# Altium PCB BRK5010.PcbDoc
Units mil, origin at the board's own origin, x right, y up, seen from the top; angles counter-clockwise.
Board outline 5314.96 x 3937.01 mil, 2 copper layers (Top Layer, Bottom Layer), stack 64.8 mil thick; 23 components, 218 nets, 546 pads, 113 vias.
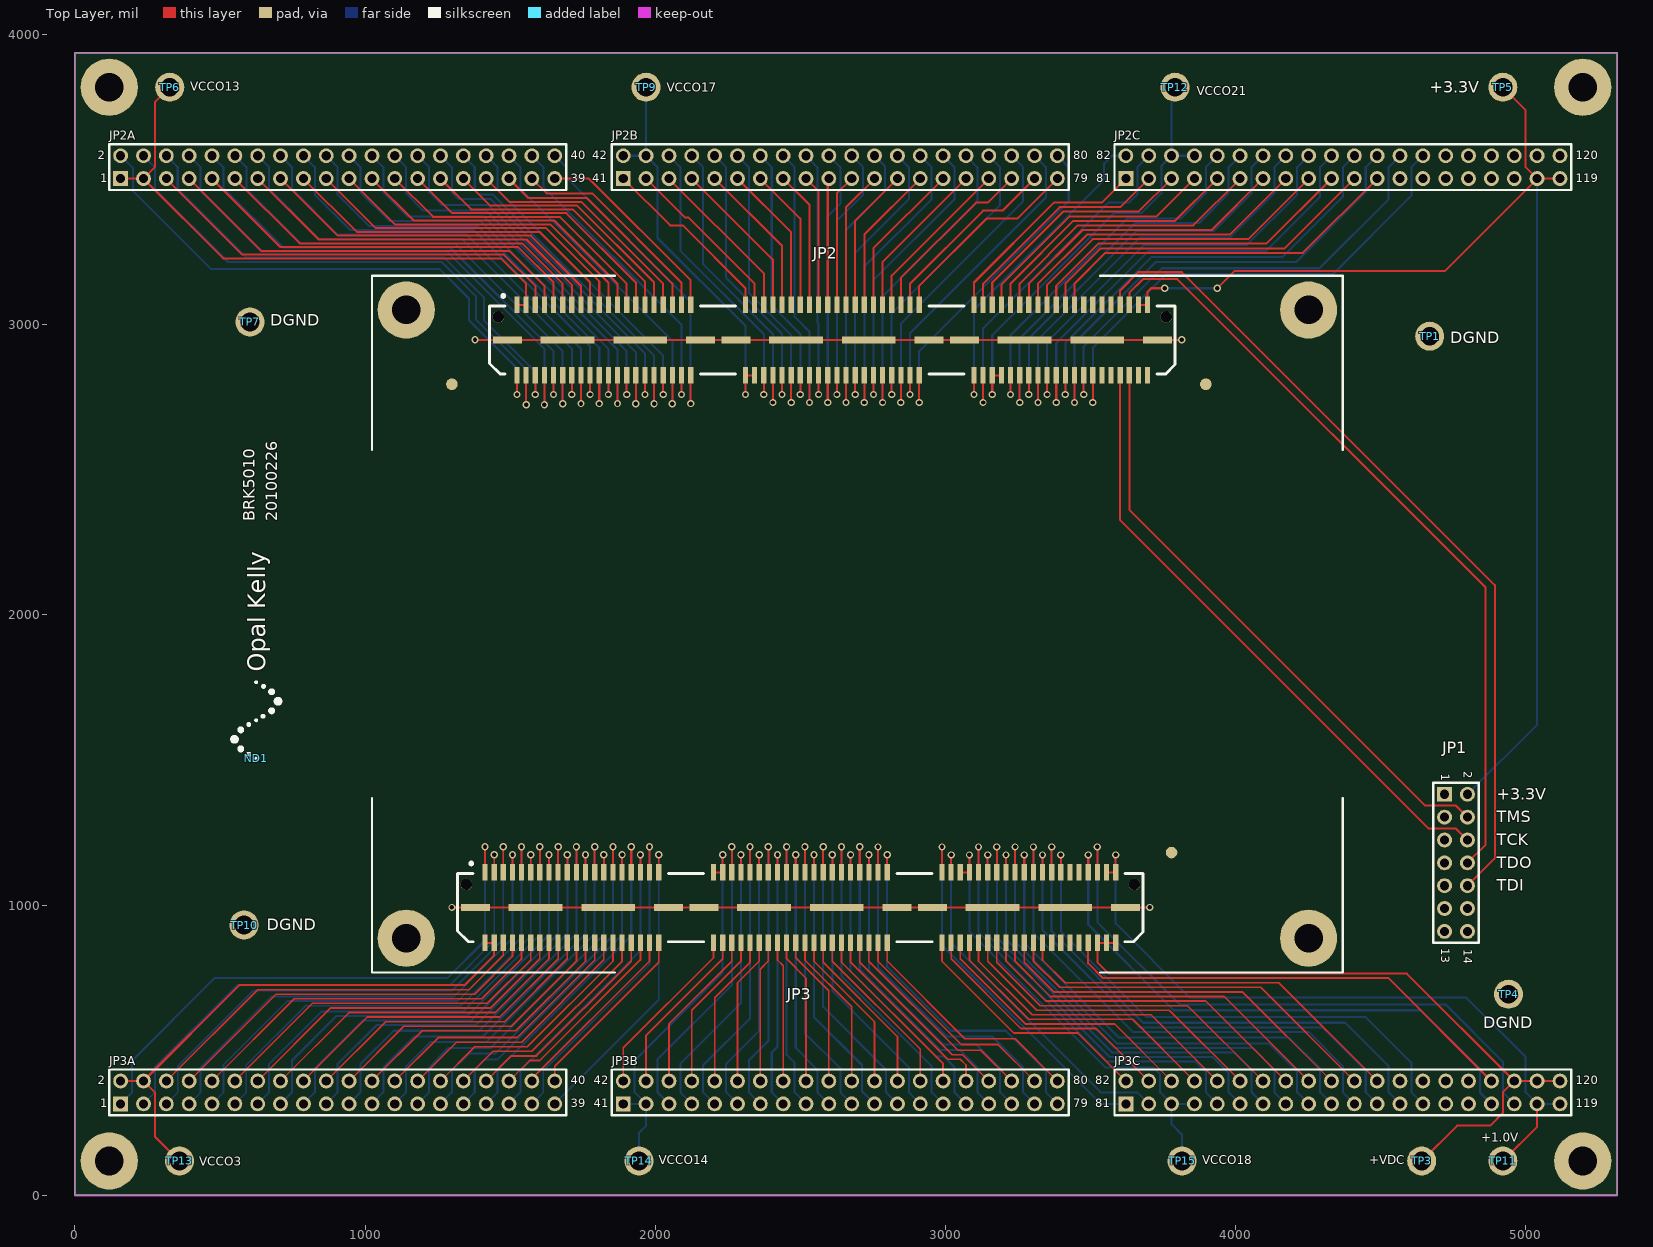
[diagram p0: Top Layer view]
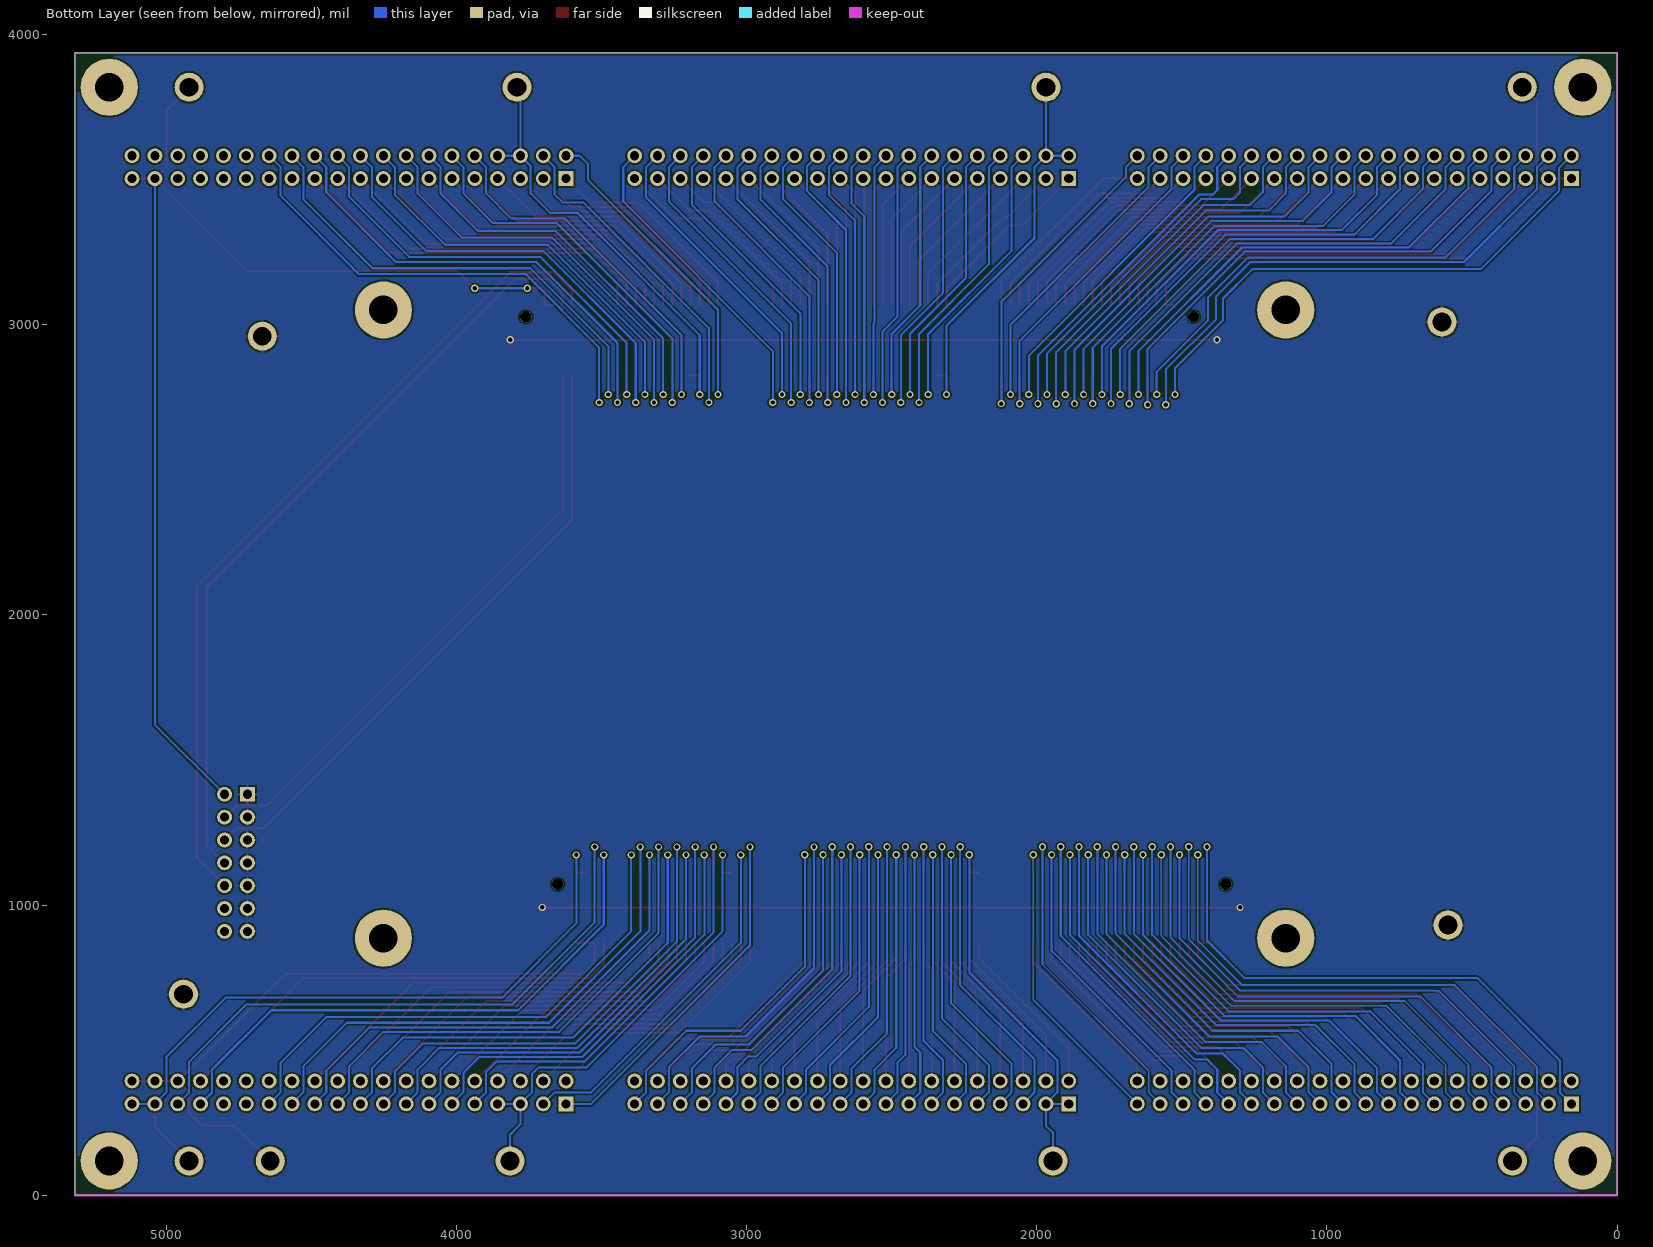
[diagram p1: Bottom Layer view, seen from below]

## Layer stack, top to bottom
Top Layer: signal copper 1.4
Dielectric: core 62, FR-4, Dk 4.8
Bottom Layer: signal copper 1.4

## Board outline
0,0 0,3937.01 5314.96,3937.01 5314.96,0

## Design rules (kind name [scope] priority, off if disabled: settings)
Clearance [All] p1: gap=6
FabricationTestPointUsage TestPointUsage [All] p1: valid=0 allowmultiple=FALSE
FabricationTestpoint Testpoint [All] p1: side=3 testpointundercomponent=TRUE minsize=40 maxsize=100 preferedsize=60 minholesize=0 maxholesize=40 preferedholesize=32 testpointgrid=1 allowsidetop=TRUE allowsidebottom=TRUE usegrid=TRUE gridtolerance=0.01
HoleSize [All] p1: absolutevalues=TRUE maxlimit=236.22 minlimit=15 maxpercent=80.000 minpercent=20.000
PolygonConnect "Via Connect" [IsVia] p1: connectstyle=Direct reliefconductorwidth=10 reliefentries=4 polygonreliefangle="90 Angle"
PolygonConnect [All] p2: connectstyle=Relief reliefconductorwidth=10 reliefentries=4 polygonreliefangle="90 Angle"
RoutingVias [All] p1: holewidth=15 width=25 viastyle="Through Hole" minholewidth=10 minwidth=20 maxholewidth=50 maxwidth=100
SilkscreenOverComponentPads [All] p1: minsilkscreentomaskgap=10
SolderMaskExpansion [All] p1: expansion=4
Width [All] p1: maxlimit=40 minlimit=6 preferedwidth=6 minimp=50.000000 maximp=50.000000 favimp=50.000000
24 further rules are at their usual default settings.

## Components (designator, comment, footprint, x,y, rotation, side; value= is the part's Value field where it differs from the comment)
JP1 "JTAGXLNX" HDR2X7-2MM 4759.84,1145.67 r270 top
JP2 "QSE/QTE-060" QTE-060-01-X-D 2216.61,2947.36 r0 top locked
JP2A "Header 20X2" HDR2X20-2MM 905.51,3543.31 r0 top
JP2B "Header 20X2" HDR2X20-2MM 2637.8,3543.31 r0 top
JP2C "Header 20X2" HDR2X20-2MM 4370.08,3543.31 r0 top
JP3 "QSE/QTE-060" QTE-060-01-X-D 2106.38,991.34 r0 top locked
JP3A "Header 20X2" HDR2X20-2MM 905.51,354.33 r0 top
JP3B "Header 20X2" HDR2X20-2MM 2637.8,354.33 r0 top
JP3C "Header 20X2" HDR2X20-2MM 4370.08,354.33 r0 top
ND1 "OKLOGO" oklogotiny 624.73,1505.69 r90 top
TP1 "TESTPOINT" TP_MED#1 4669.29,2960.63 r180 top
TP3 "TESTPOINT" TP_MED#1 4641.73,118.11 r180 top
TP4 "TESTPOINT" TP_MED#1 4940.94,692.91 r180 top
TP5 "TESTPOINT" TP_MED#1 4921.26,3818.9 r270 top
TP6 "TESTPOINT" TP_MED#1 326.77,3818.9 r180 top
TP7 "TESTPOINT" TP_MED#1 603.29,3009.77 r180 top
TP9 "TESTPOINT" TP_MED#1 1968.5,3818.9 r180 top
TP10 "TESTPOINT" TP_MED#1 582.88,931.15 r180 top
TP11 "TESTPOINT" TP_MED#2 5099.69,118.11 r180 top
TP12 "TESTPOINT" TP_MED#1 3791.34,3818.9 r180 top
TP13 "TESTPOINT" TP_MED#1 360,118.11 r180 top
TP14 "TESTPOINT" TP_MED#1 1943.92,118.11 r180 top
TP15 "TESTPOINT" TP_MED#1 3815.59,118.11 r180 top

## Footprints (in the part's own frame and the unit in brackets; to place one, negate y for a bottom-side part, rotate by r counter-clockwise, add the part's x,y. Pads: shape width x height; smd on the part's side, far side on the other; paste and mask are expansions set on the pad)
HDR2X7-2MM [mm] "2mm 2x7 header"
  rect 1.3x1.3 hole 0.8: 1(-6,-1)
  round 1.3 hole 0.8: 2(-6,1) 3(-4,-1) 4(-4,1) 5(-2,-1) 6(-2,1) 7(0,-1) 8(0,1) 9(2,-1) 10(2,1) 11(4,-1) 12(4,1) 13(6,-1) 14(6,1)
  silkscreen extent -7,-2 7,2
HDR2X20-2MM [mm] "2mm 2x20 header"
  rect 1.3x1.3 hole 0.8: 1(-19,-1)
  round 1.3 hole 0.8: 2(-19,1) 3(-17,-1) 4(-17,1) 5(-15,-1) 6(-15,1) 7(-13,-1) 8(-13,1) 9(-11,-1) 10(-11,1) 11(-9,-1) 12(-9,1) 13(-7,-1) 14(-7,1) 15(-5,-1) 16(-5,1) 17(-3,-1) 18(-3,1) 19(-1,-1) 20(-1,1) 21(1,-1) 22(1,1) 23(3,-1) 24(3,1) 25(5,-1) 26(5,1) 27(7,-1) 28(7,1) 29(9,-1) 30(9,1) 31(11,-1) 32(11,1) 33(13,-1) 34(13,1) 35(15,-1) 36(15,1) 37(17,-1) 38(17,1) 39(19,-1) 40(19,1)
  silkscreen extent -20,-2 20,2
oklogotiny [mil] "Opal Kelly silkscreen logo (50 mil)."
  silkscreen extent -3,-82 266,82
QTE-060-01-X-D [mil] "0.80mm, 120 pin Surface Mount connectors with Ground Strip"
  rect 100x25 smd paste+0: 0(-726.25,0) 0(-61.25,0) 0(61.25,0) 0(726.25,0) 0(848.75,0) 0(1513.75,0)
  rect 185x25 smd paste+0: 0(-518.75,0) 0(-268.75,0) 0(268.75,0) 0(518.75,0) 0(1056.25,0) 0(1306.25,0)
  rect 18x57 smd paste+0: 1(-693.05,121.5) 2(-693.05,-121.5) 3(-661.55,121.5) 4(-661.55,-121.5) 5(-630.05,121.5) 6(-630.05,-121.5) 7(-598.55,121.5) 8(-598.55,-121.5) 9(-567.05,121.5) 10(-567.05,-121.5) 11(-535.55,121.5) 12(-535.55,-121.5) 13(-504.05,121.5) 14(-504.05,-121.5) 15(-472.55,121.5) 16(-472.55,-121.5) 17(-441.05,121.5) 18(-441.05,-121.5) 19(-409.55,121.5) 20(-409.55,-121.5) 21(-378.05,121.5) 22(-378.05,-121.5) 23(-346.55,121.5) 24(-346.55,-121.5) 25(-315.05,121.5) 26(-315.05,-121.5) 27(-283.55,121.5) 28(-283.55,-121.5) 29(-252.05,121.5) 30(-252.05,-121.5) 31(-220.55,121.5) 32(-220.55,-121.5) 33(-189.05,121.5) 34(-189.05,-121.5) 35(-157.55,121.5) 36(-157.55,-121.5) 37(-126.05,121.5) 38(-126.05,-121.5) 39(-94.55,121.5) 40(-94.55,-121.5) 41(94.45,121.5) 42(94.45,-121.5) 43(125.95,121.5) 44(125.95,-121.5) 45(157.45,121.5) 46(157.45,-121.5) 47(188.95,121.5) 48(188.95,-121.5) 49(220.45,121.5) 50(220.45,-121.5) 51(251.95,121.5) 52(251.95,-121.5) 53(283.45,121.5) 54(283.45,-121.5) 55(314.95,121.5) 56(314.95,-121.5) 57(346.45,121.5) 58(346.45,-121.5) 59(377.95,121.5) 60(377.95,-121.5) 61(409.45,121.5) 62(409.45,-121.5) 63(440.95,121.5) 64(440.95,-121.5) 65(472.45,121.5) 66(472.45,-121.5) 67(503.95,121.5) 68(503.95,-121.5) 69(535.45,121.5) 70(535.45,-121.5) 71(566.95,121.5) 72(566.95,-121.5) 73(598.45,121.5) 74(598.45,-121.5) 75(629.95,121.5) 76(629.95,-121.5) 77(661.45,121.5) 78(661.45,-121.5) 79(692.95,121.5) 80(692.95,-121.5) 81(881.95,121.5) 82(881.95,-121.5) 83(913.45,121.5) 84(913.45,-121.5) 85(944.95,121.5) 86(944.95,-121.5) 87(976.45,121.5) 88(976.45,-121.5) 89(1007.95,121.5) 90(1007.95,-121.5) 91(1039.45,121.5) 92(1039.45,-121.5) 93(1070.95,121.5) 94(1070.95,-121.5) 95(1102.45,121.5) 96(1102.45,-121.5) 97(1133.95,121.5) 98(1133.95,-121.5) 99(1165.45,121.5) 100(1165.45,-121.5) 101(1196.95,121.5) 102(1196.95,-121.5) 103(1228.45,121.5) 104(1228.45,-121.5) 105(1259.95,121.5) 106(1259.95,-121.5) 107(1291.45,121.5) 108(1291.45,-121.5) 109(1322.95,121.5) 110(1322.95,-121.5) 111(1354.45,121.5) 112(1354.45,-121.5) 113(1385.95,121.5) 114(1385.95,-121.5) 115(1417.45,121.5) 116(1417.45,-121.5) 117(1448.95,121.5) 118(1448.95,-121.5) 119(1480.45,121.5) 120(1480.45,-121.5)
  round 40 hole 40 paste+0: N(-757.55,80) N(1544.95,80)
  silkscreen extent -788,-118 1575,157
TP_MED#1 [mil] "Testpoint - medium sized"
  round 100 hole 65: 1(0,0)
TP_MED#2 [mil] "Testpoint - medium sized"
  round 100 hole 65: 1(178.43,0)

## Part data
JP1: "Xilinx JTAG Header, 7-Pin, Dual row"
JP2 JP3: "Header/Socket - 120-pin - Edge mount, .80mm"
JP2A JP2B JP2C JP3A JP3B JP3C: "Header, 20-Pin, Dual row"
ND1: "Opal Kelly PCB Logo"
TP1 TP3 TP4 TP5 TP6 TP7 TP9 TP10 TP11 TP12 TP13 TP14 TP15: "Testpoint"

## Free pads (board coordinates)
  round 196.85 hole 98.43: 0(118.11,118.11) 0(118.11,3818.9) 0(1141.73,885.83) 0(1141.73,3051.18) 0(4251.97,885.83) 0(4251.97,3051.18) 0(5196.85,118.11) 0(5196.85,3818.9)
  round 40 smd mask+20: FD1(1299.21,2795.28) FD2(3897.64,2795.28) FD3(3779.53,1181.1)

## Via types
v1: diameter 25, hole 15, Top Layer to Bottom Layer, 113 vias

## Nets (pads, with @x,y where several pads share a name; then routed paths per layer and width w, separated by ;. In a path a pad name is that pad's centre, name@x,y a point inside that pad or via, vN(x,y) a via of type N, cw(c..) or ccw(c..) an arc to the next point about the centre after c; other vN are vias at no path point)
+1.0VDD: JP3.117 JP3.119 JP3C.37 JP3C.39 TP11.1 | length 2434
  Top Layer w7: JP3.117 JP3.119 v1(3586.83,1173.01) ; TP11.1 5039.37,236.22 JP3C.37
  Bottom Layer w7: v1(3586.83,1173.01) 3586.83,936.79 3842.52,681.1 4795.28,681.1 5000,476.38 5000,354.33 JP3C.37 JP3C.39
+3.3VDD: JP1.2 JP2.117 JP2.119 JP2C.37 JP2C.39 TP5.1 | length 4244.8
  Top Layer w7: JP2.117 JP2.119 3697.06,3114.39 3708.66,3125.98 v1(3755.91,3125.98) ; v1(3937.01,3125.98) 3996.06,3185.04 4720.47,3185.04 JP2C.37 ; TP5.1 5000,3740.16 5000,3543.31 JP2C.37 ; JP2C.39 JP2C.37
  Bottom Layer w7: v1(3755.91,3125.98) v1(3937.01,3125.98) ; JP1.2 5039.37,1622.05 JP2C.37
+VBATT: JP3.115 JP3C.35 | length 2105.9
  Top Layer w7: JP3.115 v1(3523.83,1200.58)
  Bottom Layer w7: v1(3523.83,1200.58) 3523.83,940.74 3807.09,657.48 4724.41,657.48 4921.26,460.63 4921.26,354.33 JP3C.35
+VCCO3: JP3.2 JP3.4 JP3A.2 JP3A.4 TP13.1 | length 1868.2
  Top Layer w7: JP3A.2 JP3A.4 ; TP13.1 275.59,202.52 275.59,354.33 JP3A.4 ; JP3.2 JP3.4 1444.83,826.72 1342.52,724.41 566.93,724.41 JP3A.4
+VCCO13: JP2.1 JP2.3 JP2A.1 JP2A.3 TP6.1 | length 2004.5
  Top Layer w7: JP2A.1 JP2A.3 ; TP6.1 275.59,3767.72 275.59,3543.31 JP2A.3 ; JP2.1 JP2.3 1555.06,3141.79 1467.84,3229.01 511.15,3229.01 JP2A.3
+VCCO14: JP3.41 JP3.43 JP3B.1 JP3B.3 TP14.1 | length 1377.7
  Top Layer w7: JP3.41 JP3.43 v1(2232.33,1173.18)
  Bottom Layer w7: JP3B.1 JP3B.3 ; TP14.1 1943.92,215.57 1968.5,240.16 JP3B.3 ; v1(2232.33,1173.18) 2232.33,767.76 1929.13,464.57 1929.13,354.33 JP3B.3
+VCCO17: JP2.42 JP2.44 JP2B.2 JP2B.4 TP9.1 | length 1377.2
  Top Layer w7: v1(2311.02,2759.84) v1(2311.02,2759.84) JP2.42 JP2.44
  Bottom Layer w7: JP2B.2 JP2B.4 ; TP9.1 JP2B.4 ; v1(2311.02,2759.84) 2311.02,2996.06 2007.87,3299.21 2007.87,3543.31 JP2B.4
+VCCO18: JP3.85 JP3.87 JP3C.5 JP3C.7 TP15.1 | length 1625.8
  Top Layer w7: JP3.85 JP3.87 v1(3082.83,1173.08)
  Bottom Layer w7: v1(3082.83,1173.08) 3082.83,909.3 3551.18,440.94 3716.54,440.94 3740.16,417.32 3740.16,354.33 JP3C.5 ; TP15.1 3815.59,208.03 3779.53,244.1 JP3C.5 ; JP3C.7 JP3C.5
+VCCO21: JP2.86 JP2.88 JP2C.6 JP2C.8 TP12.1 | length 1534.4
  Top Layer w7: v1(3161.56,2759.99) JP2.86 JP2.88
  Bottom Layer w7: v1(3161.56,2759.99) 3161.56,2964.55 3582.84,3385.83 3677.17,3385.83 3744.09,3452.76 3744.09,3547.24 JP2C.6 ; TP12.1@3779.53,3807.09 JP2C.6 ; JP2C.8 JP2C.6
+VDC: JP3.116 JP3.118 JP3.120 JP3C.36 JP3C.38 JP3C.40 TP3.1 | length 2368.3
  Top Layer w7: JP3.120 JP3.118 JP3.116 3523.83,802.94 3562.99,763.78 4590.55,763.78 JP3C.36 ; TP3.1 4763.78,240.16 4877.95,240.16 4921.26,283.46 4921.26,354.33 JP3C.36 ; JP3C.40 JP3C.38 JP3C.36
DGND: JP1.1 JP1.3 JP1.5 JP1.7 JP1.9 JP1.11 JP1.13 JP2.0 JP3.0 TP1.1 TP4.1 TP7.1 TP10.1 | length 4843.4
  Top Layer w7: v1(1299.21,992.13) 1300,991.34 1380.13,991.34 1587.63,991.34 1837.63,991.34 2045.13,991.34 2167.63,991.34 2375.13,991.34 2625.13,991.34 2832.63,991.34 2955.13,991.34 3162.63,991.34 3412.63,991.34 3620.13,991.34 3703.94,991.34 v1(3704.72,992.13) ; v1(1378.98,2948.82) 1380.43,2947.36 1490.36,2947.36 1697.86,2947.36 1947.86,2947.36 2155.36,2947.36 2277.86,2947.36 2485.36,2947.36 2735.36,2947.36 2942.86,2947.36 3065.36,2947.36 3272.86,2947.36 3522.86,2947.36 3730.36,2947.36 3813.5,2947.36 v1(3814.96,2948.82)
JP2_2: JP2.2 JP2A.2 | length 1916.1
  Top Layer w7: v1(1523.56,2759.78) JP2.2
  Bottom Layer w7: JP2A.2 200.79,3539.37 200.79,3460.63 468.5,3192.91 1255.91,3192.91 1358.27,3090.55 1358.27,3015.75 1523.56,2850.45 v1(1523.56,2759.78)
JP2_4: JP2.4 JP2A.4 | length 1937.3
  Top Layer w7: JP2.4 1555.06,2724.46 v1(1555.12,2724.41)
  Bottom Layer w7: JP2A.4 275.59,3543.31 275.59,3468.5 527.56,3216.54 1263.78,3216.54 1381.89,3098.43 1381.89,3019.68 1555.12,2846.46 v1(1555.12,2724.41)
JP2_5: JP2.5 JP2A.5 | length 1489.9
  Top Layer w7: JP2A.5 576.89,3242.01 1478.46,3242.01 1586.56,3133.91 JP2.5
JP2_6: JP2.6 JP2A.6 | length 1814.4
  Top Layer w7: v1(1586.56,2759.89) JP2.6
  Bottom Layer w7: JP2A.6 354.33,3543.31 354.33,3468.5 590.55,3232.28 1271.65,3232.28 1409.45,3094.49 1409.45,3015.75 1586.56,2838.63 v1(1586.56,2759.89)
JP2_7: JP2.7 JP2A.7 | length 1442.7
  Top Layer w7: JP2A.7 642.63,3255.01 1496.96,3255.01 1618.06,3133.9 JP2.7
JP2_8: JP2.8 JP2A.8 | length 1842.7
  Top Layer w7: v1(1618.06,2724.46) JP2.8
  Bottom Layer w7: JP2A.8 433.07,3543.31 433.07,3460.63 641.73,3251.97 1283.46,3251.97 1618.06,2917.37 v1(1618.06,2724.46)
JP2_9: JP2.9 JP2A.9 | length 1402.4
  Top Layer w7: JP2A.9 708.37,3268.01 1527.27,3268.01 1649.56,3145.71 JP2.9
JP2_10: JP2.10 JP2A.10 | length 1713.1
  Top Layer w7: v1(1649.56,2759.88) JP2.10
  Bottom Layer w7: JP2A.10 511.81,3543.31 511.81,3472.44 717.72,3266.53 1292.53,3266.53 1649.56,2909.49 v1(1649.56,2759.88)
JP2_11: JP2.11 JP2A.11 | length 1352.8
  Top Layer w7: JP2A.11 774.11,3281.01 1541.83,3281.01 1681.06,3141.77 JP2.11
JP2_12: JP2.12 JP2A.12 | length 1731.3
  Top Layer w7: v1(1681.06,2728.31) JP2.12
  Bottom Layer w7: JP2A.12 590.55,3543.31 590.55,3468.5 779.53,3279.53 1311.02,3279.53 1681.06,2909.49 v1(1681.06,2728.31)
JP2_13: JP2.13 JP2A.13 | length 1303.3
  Top Layer w7: JP2A.13 839.85,3294.01 1556.39,3294.01 1712.56,3137.83 JP2.13
JP2_14: JP2.14 JP2A.14 | length 1625.5
  Top Layer w7: v1(1712.56,2759.88) JP2.14
  Bottom Layer w7: JP2A.14 669.29,3543.31 669.29,3468.5 842.52,3295.28 1334.65,3295.28 1712.56,2917.36 v1(1712.56,2759.88)
JP2_15: JP2.15 JP2A.15 | length 1253.7
  Top Layer w7: JP2A.15 905.59,3307.01 1570.94,3307.01 1744.06,3133.89 JP2.15
JP2_16: JP2.16 JP2A.16 | length 1641.3
  Top Layer w7: v1(1744.06,2728.38) JP2.16
  Bottom Layer w7: JP2A.16 748.03,3543.31 748.03,3468.5 905.51,3311.02 1350.39,3311.02 1641.73,3019.68 1744.06,2917.35 v1(1744.06,2728.38)
JP2_17: JP2.17 JP2A.17 | length 1213.4
  Top Layer w7: JP2A.17 971.33,3320.01 1601.25,3320.01 1775.56,3145.7 JP2.17
JP2_18: JP2.18 JP2A.18 | length 1547.2
  Top Layer w7: v1(1775.56,2759.87) JP2.18
  Bottom Layer w7: JP2A.18 826.77,3543.31 826.77,3448.82 948.82,3326.77 1374.02,3326.77 1775.56,2925.22 v1(1775.56,2759.87)
JP2_19: JP2.19 JP2A.19 | length 1168.4
  Top Layer w7: JP2A.19 1037.07,3333.01 1623.68,3333.01 1807.06,3149.63 JP2.19
JP2_20: JP2.20 JP2A.20 | length 1560.6
  Top Layer w7: v1(1807.06,2728.37) JP2.20
  Bottom Layer w7: JP2A.20 905.51,3543.31 905.51,3448.82 1014.56,3339.77 1388.57,3339.77 1807.06,2921.28 v1(1807.06,2728.37)
JP2_21: JP2.21 JP2A.21 | length 1118.9
  Top Layer w7: JP2A.21 1102.81,3346.01 1638.24,3346.01 1838.56,3145.69 JP2.21
JP2_22: JP2.22 JP2A.22 | length 1443.5
  Top Layer w7: v1(1838.56,2759.86) JP2.22
  Bottom Layer w7: JP2A.22 984.25,3543.31 984.25,3456.69 1082.68,3358.27 1397.64,3358.27 1838.56,2917.34 v1(1838.56,2759.86)
JP2_23: JP2.23 JP2A.23 | length 1069.4
  Top Layer w7: JP2A.23 1168.55,3359.01 1652.8,3359.01 1870.06,3141.75 JP2.23
JP2_24: JP2.24 JP2A.24 | length 1456.9
  Top Layer w7: v1(1870.06,2728.36) JP2.24
  Bottom Layer w7: JP2A.24 1062.99,3543.31 1062.99,3456.69 1145.67,3374.02 1409.45,3374.02 1870.06,2913.4 v1(1870.06,2728.36)
JP2_25: JP2.25 JP2A.25 | length 1022.1
  Top Layer w7: JP2A.25 1234.29,3372.01 1671.3,3372.01 1901.56,3141.74 JP2.25
JP2_26: JP2.26 JP2A.26 | length 1346.7
  Top Layer w7: v1(1901.56,2759.85) JP2.26
  Bottom Layer w7: JP2A.26 1141.73,3543.31 1141.73,3452.76 1200.79,3393.7 1417.32,3393.7 1901.56,2909.46 v1(1901.56,2759.85)
JP2_27: JP2.27 JP2A.27 | length 977.2
  Top Layer w7: JP2A.27 1300.03,3385.01 1693.73,3385.01 1933.06,3145.68 JP2.27
JP2_28: JP2.28 JP2A.28 | length 1357.9
  Top Layer w7: v1(1933.06,2728.35) JP2.28
  Bottom Layer w7: JP2A.28 1220.47,3543.31 1220.47,3456.69 1263.78,3413.39 1425.2,3413.39 1933.06,2905.52 v1(1933.06,2728.35)
JP2_29: JP2.29 JP2A.29 | length 932.2
  Top Layer w7: JP2A.29 1365.77,3398.01 1716.17,3398.01 1964.56,3149.61 JP2.29
JP2_30: JP2.30 JP2A.30 | length 1245.3
  Top Layer w7: v1(1964.56,2759.85) JP2.30
  Bottom Layer w7: JP2A.30 1299.21,3543.31 1299.21,3456.69 1322.83,3433.07 1433.07,3433.07 1964.56,2901.58 v1(1964.56,2759.85)
JP2_31: JP2.31 JP2A.31 | length 882.7
  Top Layer w7: JP2A.31 1431.51,3411.01 1730.72,3411.01 1996.06,3145.67 JP2.31
JP2_32: JP2.32 JP2A.32 | length 1251.9
  Top Layer w7: v1(1996.06,2728.35) JP2.32
  Bottom Layer w7: JP2A.32 1377.95,3543.31 1377.95,3464.57 1393.7,3448.82 1440.94,3448.82 1996.06,2893.7 v1(1996.06,2728.35)
JP2_33: JP2.33 JP2A.33 | length 833.1
  Top Layer w7: JP2A.33 1497.25,3424.01 1745.28,3424.01 2027.56,3141.73 JP2.33
JP2_34: JP2.34 JP2A.34 | length 1141.6
  Top Layer w7: v1(2027.56,2759.85) JP2.34
  Bottom Layer w7: JP2A.34 1456.69,3543.31 1456.69,3464.57 2027.56,2893.7 v1(2027.56,2759.85)
JP2_35: JP2.35 JP2A.35 | length 785.9
  Top Layer w7: JP2A.35 1562.99,3437.01 1763.78,3437.01 2059.06,3141.72 JP2.35
JP2_36: JP2.36 JP2A.36 | length 1185
  Top Layer w7: v1(2059.06,2728.36) JP2.36
  Bottom Layer w7: JP2A.36 1535.43,3543.31 1535.43,3468.5 2059.06,2944.87 v1(2059.06,2728.36)
JP2_37: JP2.37 JP2A.37 | length 741
  Top Layer w7: JP2A.37 1625.98,3452.76 1783.46,3452.76 2090.56,3145.66 JP2.37
JP2_38: JP2.38 JP2A.38 | length 1102.5
  Top Layer w7: v1(2090.56,2759.86) JP2.38
  Bottom Layer w7: JP2A.38 1614.17,3543.31 1614.17,3476.38 2090.56,2999.99 v1(2090.56,2759.86)
JP2_39: JP2.39 JP2A.39 | length 698.3
  Top Layer w7: JP2A.39 1771.65,3503.94 2122.06,3153.53 JP2.39
JP2_40: JP2.40 JP2A.40 | length 1145.9
  Top Layer w7: v1(2122.06,2728.36) JP2.40
  Bottom Layer w7: JP2A.40 1692.91,3543.31 1692.91,3507.87 2122.06,3078.72 v1(2122.06,2728.36)
JP2_41: JP2.41 JP2B.1 | length 635
  Top Layer w7: JP2B.1 2051.18,3342.52 2094.49,3342.52 2311.06,3125.94 JP2.41
JP2_43: JP2.43 JP2B.3 | length 596.9
  Top Layer w7: JP2B.3 2102.36,3370.08 2114.17,3370.08 2342.56,3141.69 JP2.43
JP2_45: JP2.45 JP2B.5 | length 570.4
  Top Layer w7: JP2B.5 2374.06,3177.12 JP2.45
JP2_46: JP2.46 JP2B.6 | length 1024.1
  Top Layer w7: v1(2374.06,2759.89) JP2.46
  Bottom Layer w7: JP2B.6 2086.61,3543.31 2086.61,3255.91 2374.06,2968.46 v1(2374.06,2759.89)
JP2_47: JP2.47 JP2B.7 | length 550.9
  Top Layer w7: JP2B.7 2405.56,3224.36 JP2.47
JP2_48: JP2.48 JP2B.8 | length 1059.9
  Top Layer w7: v1(2405.56,2732.23) JP2.48
  Bottom Layer w7: JP2B.8 2165.35,3543.31 2165.35,3208.66 2405.56,2968.45 v1(2405.56,2732.23)
JP2_49: JP2.49 JP2B.9 | length 531.3
  Top Layer w7: JP2B.9 2437.06,3271.6 JP2.49
JP2_50: JP2.50 JP2B.10 | length 985
  Top Layer w7: v1(2437.06,2759.9) JP2.50
  Bottom Layer w7: JP2B.10 2244.09,3543.31 2244.09,3161.42 2437.06,2968.45 v1(2437.06,2759.9)
JP2_51: JP2.51 JP2B.11 | length 511.7
  Top Layer w7: JP2B.11 2468.56,3318.84 JP2.51
JP2_52: JP2.52 JP2B.12 | length 1020.5
  Top Layer w7: v1(2468.56,2732.34) JP2.52
  Bottom Layer w7: JP2B.12 2322.83,3543.31 2322.83,3110.24 2468.56,2964.51 v1(2468.56,2732.34)
JP2_53: JP2.53 JP2B.13 | length 492.2
  Top Layer w7: JP2B.13 2500.06,3366.08 JP2.53
JP2_54: JP2.54 JP2B.14 | length 945.8
  Top Layer w7: v1(2500.06,2759.91) JP2.54
  Bottom Layer w7: JP2B.14 2401.57,3543.31 2401.57,3066.93 2500.06,2968.44 v1(2500.06,2759.91)
JP2_55: JP2.55 JP2B.15 | length 472.6
  Top Layer w7: JP2B.15 2531.56,3413.32 JP2.55
JP2_56: JP2.56 JP2B.16 | length 981.4
  Top Layer w7: v1(2531.56,2732.35) JP2.56
  Bottom Layer w7: JP2B.16 2480.32,3543.31 2480.32,3027.56 2531.56,2976.31 v1(2531.56,2732.35)
JP2_57: JP2.57 JP2B.17 | length 453
  Top Layer w7: JP2B.17 2563.06,3460.56 JP2.57
JP2_58: JP2.58 JP2B.18 | length 906.7
  Top Layer w7: v1(2563.06,2759.91) JP2.58
  Bottom Layer w7: JP2B.18 2559.06,3543.31 2559.06,3007.87 2563.06,3003.87 v1(2563.06,2759.91)
JP2_59: JP2.59 JP2B.19 | length 436.7
  Top Layer w7: JP2.59 2594.56,3500.08 JP2B.19
JP2_60: JP2.60 JP2B.20 | length 978
  Top Layer w7: v1(2594.56,2732.36) JP2.60
  Bottom Layer w7: v1(2594.56,2732.36) 2594.56,3374.09 2637.8,3417.32 2637.8,3543.31 JP2B.20
JP2_61: JP2.61 JP2B.21 | length 456.2
  Top Layer w7: JP2.61 2626.06,3452.84 JP2B.21
JP2_62: JP2.62 JP2B.22 | length 942.5
  Top Layer w7: v1(2626.06,2759.92) JP2.62
  Bottom Layer w7: v1(2626.06,2759.92) 2626.06,3358.35 2716.54,3448.82 2716.54,3543.31 JP2B.22
JP2_63: JP2.63 JP2B.23 | length 475.8
  Top Layer w7: JP2.63 2657.56,3405.6 JP2B.23
JP2_64: JP2.64 JP2B.24 | length 1013.9
  Top Layer w7: v1(2657.56,2732.37) JP2.64
  Bottom Layer w7: v1(2657.56,2732.37) 2657.56,3326.86 2791.34,3460.63 2791.34,3547.24 JP2B.24
JP2_65: JP2.65 JP2B.25 | length 495.4
  Top Layer w7: JP2.65 2689.06,3358.36 JP2B.25
JP2_66: JP2.66 JP2B.26 | length 981.6
  Top Layer w7: v1(2689.06,2759.93) JP2.66
  Bottom Layer w7: v1(2689.06,2759.93) 2689.06,3248.12 2874.02,3433.07 2874.02,3543.31 JP2B.26
JP2_67: JP2.67 JP2B.27 | length 514.9
  Top Layer w7: JP2.67 2720.56,3311.12 JP2B.27
JP2_68: JP2.68 JP2B.28 | length 1056.3
  Top Layer w7: v1(2720.56,2732.38) JP2.68
  Bottom Layer w7: v1(2720.56,2732.38) 2720.56,3200.88 2952.76,3433.07 2952.76,3543.31 JP2B.28
JP2_69: JP2.69 JP2B.29 | length 534.5
  Top Layer w7: JP2.69 2752.06,3263.88 JP2B.29
JP2_70: JP2.70 JP2B.30 | length 1020.7
  Top Layer w7: v1(2752.06,2759.94) JP2.70
  Bottom Layer w7: v1(2752.06,2759.94) 2752.06,3153.64 3031.5,3433.07 3031.5,3543.31 JP2B.30
JP2_71: JP2.71 JP2B.31 | length 554.1
  Top Layer w7: JP2.71 2783.56,3216.64 JP2B.31
JP2_72: JP2.72 JP2B.32 | length 1095.4
  Top Layer w7: v1(2783.56,2732.38) JP2.72
  Bottom Layer w7: v1(2783.56,2732.38) 2783.56,3098.52 3110.24,3425.2 3110.24,3543.31 JP2B.32
JP2_73: JP2.73 JP2B.33 | length 573.6
  Top Layer w7: JP2.73 2815.06,3169.39 JP2B.33
JP2_74: JP2.74 JP2B.34 | length 1059.8
  Top Layer w7: v1(2815.06,2759.95) JP2.74
  Bottom Layer w7: v1(2815.06,2759.95) 2815.06,3039.47 3188.98,3413.39 3188.98,3543.31 JP2B.34
JP2_75: JP2.75 JP2B.35 | length 616.3
  Top Layer w7: JP2.75 2846.56,3161.52 3106.3,3421.26 3145.67,3421.26 JP2B.35
JP2_76: JP2.76 JP2B.36 | length 1134.5
  Top Layer w7: v1(2846.56,2732.39) JP2.76
  Bottom Layer w7: v1(2846.56,2732.39) 2846.56,3004.04 3267.72,3425.2 3267.72,3543.31 JP2B.36
JP2_77: JP2.77 JP2B.37 | length 652
  Top Layer w7: JP2.77 2878.06,3141.84 3129.92,3393.7 3196.85,3393.7 JP2B.37
JP2_78: JP2.78 JP2B.38 | length 1099
  Top Layer w7: v1(2878.06,2759.95) JP2.78
  Bottom Layer w7: v1(2878.06,2759.95) 2878.06,2970.49 3346.46,3438.88 3346.46,3543.31 JP2B.38
JP2_79: JP2.79 JP2B.39 | length 694.6
  Top Layer w7: JP2.79 2909.56,3133.97 3141.73,3366.14 3248.03,3366.14 JP2B.39
JP2_80: JP2.80 JP2B.40 | length 1173.6
  Top Layer w7: v1(2909.56,2732.4) JP2.80
  Bottom Layer w7: v1(2909.56,2732.4) 2909.56,2909.56 3425.2,3425.2 3425.2,3543.31 JP2B.40
JP2_81: JP2.81 JP2C.1 | length 748.8
  Top Layer w7: JP2.81 3098.56,3145.81 3374.02,3421.26 3539.37,3421.26 JP2C.1
JP2_82: JP2.82 JP2C.2 | length 1133.1
  Top Layer w7: v1(3098.56,2759.98) JP2.82
  Bottom Layer w7: v1(3098.56,2759.98) 3098.56,3051.32 3547.24,3500 3547.24,3555.12 3574.8,3582.68 JP2C.2
JP2_83: JP2.83 JP2C.3 | length 793.7
  Top Layer w7: JP2.83 3130.06,3141.88 3393.7,3405.51 3602.36,3405.51 JP2C.3
JP2_84: JP2.84 JP2C.4 | length 1221.6
  Top Layer w7: v1(3130.06,2732.43) JP2.84
  Bottom Layer w7: v1(3130.06,2732.43) 3130.06,2988.33 3563.53,3421.79 3634.39,3421.79 3661.42,3448.82 3661.42,3543.31 JP2C.4
JP2_85: JP2.85 JP2C.5 | length 843.3
  Top Layer w7: JP2.85 3161.56,3145.82 3405.51,3389.76 3665.35,3389.76 JP2C.5
JP2_86: JP2.90 JP2C.10 | length 1292.5
  Top Layer w7: v1(3224.41,2759.84) 3224.56,2760 JP2.90
  Bottom Layer w7: v1(3224.41,2759.84) 3224.41,2964.57 3625.98,3366.14 3811.02,3366.14 3897.64,3452.76 3897.64,3543.31 JP2C.10
JP2_87: JP2.87 JP2C.7 | length 885.9
  Top Layer w7: JP2.87 3193.06,3137.95 3429.13,3374.02 3728.35,3374.02 JP2C.7
JP2_88: JP2.92 JP2C.12 | length 1387.9
  Top Layer w7: v1(3255.91,2732.28) 3256.06,2732.44 JP2.92
  Bottom Layer w7: v1(3255.91,2732.28) 3255.91,2952.76 3653.54,3350.39 3874.02,3350.39 3976.38,3452.76 3976.38,3543.31 JP2C.12
JP2_89: JP2.89 JP2C.9 | length 935.4
  Top Layer w7: JP2.89 3224.56,3141.89 3440.94,3358.27 3791.34,3358.27 JP2C.9
JP2_90: JP2.94 JP2C.14 | length 1379.6
  Top Layer w7: v1(3287.56,2760) JP2.94
  Bottom Layer w7: v1(3287.56,2760) 3287.56,2952.92 3657.48,3322.83 3925.2,3322.83 4055.12,3452.76 4055.12,3543.31 JP2C.14
JP2_91: JP2.91 JP2C.11 | length 982.7
  Top Layer w7: JP2.91 3256.06,3141.89 3456.69,3342.52 3854.33,3342.52 JP2C.11
JP2_92: JP2.96 JP2C.16 | length 1479.6
  Top Layer w7: v1(3319.06,2732.45) JP2.96
  Bottom Layer w7: v1(3319.06,2732.45) 3319.06,2948.99 3671.26,3301.18 3982.28,3301.18 4133.86,3452.76 4133.86,3543.31 JP2C.16
JP2_93: JP2.93 JP2C.13 | length 1029.9
  Top Layer w7: JP2.93 3287.56,3141.89 3472.44,3326.77 3917.32,3326.77 JP2C.13
JP2_94: JP2.98 JP2C.18 | length 1469.4
  Top Layer w7: v1(3350.56,2760.01) JP2.98
  Bottom Layer w7: v1(3350.56,2760.01) 3350.56,2941.12 3685.04,3275.59 4039.37,3275.59 4212.6,3448.82 4212.6,3543.31 JP2C.18
JP2_95: JP2.95 JP2C.15 | length 1077.2
  Top Layer w7: JP2.95 3319.06,3141.9 3488.19,3311.02 3980.32,3311.02 JP2C.15
JP2_96: JP2.100 JP2C.20 | length 1574.1
  Top Layer w7: v1(3382.06,2732.46) JP2.100
  Bottom Layer w7: v1(3382.06,2732.46) 3382.06,2937.18 3698.82,3253.94 4104.33,3253.94 4291.34,3440.94 4291.34,3543.31 JP2C.20
JP2_97: JP2.97 JP2C.17 | length 1122.1
  Top Layer w7: JP2.97 3350.56,3137.97 3507.87,3295.28 4043.31,3295.28 JP2C.17
JP2_98: JP2.102 JP2C.22 | length 1566.2
  Top Layer w7: v1(3413.56,2760.02) JP2.102
  Bottom Layer w7: v1(3413.56,2760.02) 3413.56,2937.19 3710.63,3234.25 4163.39,3234.25 4370.08,3440.94 4370.08,3543.31 JP2C.22
JP2_99: JP2.99 JP2C.19 | length 1167
  Top Layer w7: JP2.99 3382.06,3134.03 3527.56,3279.53 4106.3,3279.53 JP2C.19
JP2_100: JP2.104 JP2C.24 | length 1659.4
  Top Layer w7: v1(3445.06,2732.47) JP2.104
  Bottom Layer w7: v1(3445.06,2732.47) 3445.06,2937.19 3724.41,3216.54 4208.66,3216.54 4448.82,3456.69 4448.82,3543.31 JP2C.24
JP2_101: JP2.101 JP2C.21 | length 1218.9
  Top Layer w7: JP2.101 3413.56,3141.91 3535.43,3263.78 4169.29,3263.78 JP2C.21
JP2_102: JP2.106 JP2C.26 | length 1658.4
  Top Layer w7: v1(3476.56,2760.03) JP2.106
  Bottom Layer w7: v1(3476.56,2760.03) 3476.56,2925.38 3746.06,3194.88 4289.37,3194.88 4527.56,3433.07 4527.56,3543.31 JP2C.26
JP2_103: JP2.103 JP2C.23 | length 1266.1
  Top Layer w7: JP2.103 3445.06,3141.91 3551.18,3248.03 4232.28,3248.03 JP2C.23
JP2_104: JP2.108 JP2C.28 | length 1751.5
  Top Layer w7: v1(3508.06,2732.47) JP2.108
  Bottom Layer w7: v1(3508.06,2732.47) 3508.06,2921.45 3761.81,3175.2 4336.61,3175.2 4606.3,3444.88 4606.3,3543.31 JP2C.28
JP3_1: JP3.1 JP3A.1 | length 1964.3
  Top Layer w7: JP3.1 v1(1413.33,1200.73)
  Bottom Layer w7: JP3A.1 196.85,354.33 196.85,464.57 480.31,748.03 1283.46,748.03 1413.33,877.89 v1(1413.33,1200.73)
JP3_3: JP3.3 JP3A.3 | length 1848.1
  Top Layer w6: JP3.3 v1(1444.83,1173.17)
  Bottom Layer w6: JP3A.3 275.59,354.33 275.59,440.94 559.06,724.41 1291.34,724.41 1444.83,877.9 v1(1444.83,1173.17)
JP3_5: JP3.5 JP3A.5 | length 1856
  Top Layer w6: JP3.5 v1(1476.33,1200.74)
  Bottom Layer w6: JP3A.5 354.33,354.33 354.33,444.88 614.17,704.72 1299.21,704.72 1476.33,881.84 v1(1476.33,1200.74)
JP3_6: JP3.6 JP3A.6 | length 1383.8
  Top Layer w6: JP3A.6 629.92,708.66 1358.27,708.66 1476.33,826.72 JP3.6
JP3_7: JP3.7 JP3A.7 | length 1749.1
  Top Layer w6: JP3.7 v1(1507.83,1173.18)
  Bottom Layer w6: JP3A.7 433.07,354.33 433.07,440.94 677.17,685.04 1307.09,685.04 1507.83,885.78 v1(1507.83,1173.18)
JP3_8: JP3.8 JP3A.8 | length 1338.9
  Top Layer w6: JP3A.8 692.91,692.91 1377.95,692.91 1507.83,822.79 JP3.8
JP3_9: JP3.9 JP3A.9 | length 1759.2
  Top Layer w6: JP3.9 v1(1539.33,1200.75)
  Bottom Layer w6: JP3A.9 511.81,354.33 511.81,448.82 732.28,669.29 1318.9,669.29 1539.33,889.72 v1(1539.33,1200.75)
JP3_10: JP3.10 JP3A.10 | length 1296.2
  Top Layer w6: JP3A.10 755.91,677.16 1401.49,677.16 1539.33,815 JP3.10
JP3_11: JP3.11 JP3A.11 | length 1654.6
  Top Layer w6: JP3.11 v1(1570.83,1173.19)
  Bottom Layer w6: JP3A.11 590.55,354.33 590.55,448.82 795.28,653.54 1330.71,653.54 1570.83,893.66 v1(1570.83,1173.19)
JP3_12: JP3.12 JP3A.12 | length 1251.3
  Top Layer w6: JP3A.12 818.9,661.42 1421.26,661.42 1570.83,810.99 JP3.12
JP3_13: JP3.13 JP3A.13 | length 1662.5
  Top Layer w7: JP3.13 v1(1602.33,1200.75)
  Bottom Layer w7: JP3A.13 669.29,354.33 669.29,452.76 850.39,633.86 1338.58,633.86 1602.33,897.6 v1(1602.33,1200.75)
JP3_14: JP3.14 JP3A.14 | length 1201.8
  Top Layer w6: JP3A.14 881.89,645.67 1433.07,645.67 1602.33,814.93 JP3.14
JP3_15: JP3.15 JP3A.15 | length 1567
  Top Layer w7: JP3.15 v1(1633.83,1173.2)
  Bottom Layer w7: JP3A.15 748.03,354.33 748.03,464.57 901.57,618.11 1354.33,618.11 1633.83,897.61 v1(1633.83,1173.2)
JP3_16: JP3.16 JP3A.16 | length 1154.6
  Top Layer w6: JP3A.16 944.88,629.92 1448.82,629.92 1633.83,814.93 JP3.16
JP3_17: JP3.17 JP3A.17 | length 1556.5
  Top Layer w7: JP3.17 v1(1665.33,1200.76)
  Bottom Layer w7: JP3A.17 826.77,354.33 826.77,437.01 992.13,602.36 1366.14,602.36 1665.33,901.55 v1(1665.33,1200.76)
JP3_18: JP3.18 JP3A.18 | length 1107.3
  Top Layer w6: JP3A.18 1007.87,614.17 1464.57,614.17 1665.33,814.93 JP3.18
JP3_19: JP3.19 JP3A.19 | length 1463.3
  Top Layer w7: JP3.19 v1(1696.83,1173.21)
  Bottom Layer w7: JP3A.19 905.51,354.33 905.51,452.76 1039.37,586.61 1381.89,586.61 1696.83,901.55 v1(1696.83,1173.21)
JP3_20: JP3.20 JP3A.20 | length 1060.1
  Top Layer w6: JP3A.20 1070.87,598.42 1480.31,598.42 1696.83,814.94 JP3.20
JP3_21: JP3.21 JP3A.21 | length 1471.2
  Top Layer w7: JP3.21 v1(1728.33,1200.77)
  Bottom Layer w7: JP3A.21 984.25,354.33 984.25,452.76 1098.43,566.93 1393.7,566.93 1728.33,901.56 v1(1728.33,1200.77)
JP3_22: JP3.22 JP3A.22 | length 1017.4
  Top Layer w6: JP3A.22 1133.86,582.68 1503.94,582.68 1728.33,807.07 JP3.22
JP3_23: JP3.23 JP3A.23 | length 1362
  Top Layer w7: JP3.23 v1(1759.83,1173.21)
  Bottom Layer w7: JP3A.23 1062.99,354.33 1062.99,440.94 1169.29,547.24 1405.51,547.24 1759.83,901.56 v1(1759.83,1173.21)
JP3_24: JP3.24 JP3A.24 | length 970.2
  Top Layer w6: JP3A.24 1196.85,566.93 1519.68,566.93 1759.83,807.07 JP3.24
JP3_25: JP3.25 JP3A.25 | length 1372.1
  Top Layer w7: JP3.25 v1(1791.33,1200.78)
  Bottom Layer w7: JP3A.25 1141.73,354.33 1141.73,444.88 1224.41,527.56 1417.32,527.56 1791.33,901.56 v1(1791.33,1200.78)
JP3_26: JP3.26 JP3A.26 | length 920.6
  Top Layer w6: JP3A.26 1251.97,543.31 1523.62,543.31 1791.33,811.01 JP3.26
JP3_27: JP3.27 JP3A.27 | length 1269.8
  Top Layer w7: JP3.27 v1(1822.83,1173.22)
  Bottom Layer w7: JP3A.27 1220.47,354.33 1220.47,440.94 1287.4,507.87 1433.07,507.87 1822.83,897.63 v1(1822.83,1173.22)
JP3_28: JP3.28 JP3A.28 | length 873.4
  Top Layer w6: JP3A.28 1314.96,527.56 1539.37,527.56 1822.83,811.02 JP3.28
JP3_29: JP3.29 JP3A.29 | length 1273.1
  Top Layer w7: JP3.29 v1(1854.33,1200.78)
  Bottom Layer w7: JP3A.29 1299.21,354.33 1299.21,429.13 1358.27,488.19 1448.82,488.19 1854.33,893.7 v1(1854.33,1200.78)
JP3_30: JP3.30 JP3A.30 | length 828.5
  Top Layer w6: JP3A.30 1377.95,511.81 1559.06,511.81 1854.33,807.08 JP3.30
JP3_31: JP3.31 JP3A.31 | length 1170.7
  Top Layer w7: JP3.31 v1(1885.83,1173.23)
  Bottom Layer w7: JP3A.31 1377.95,354.33 1377.95,433.07 1413.39,468.5 1456.69,468.5 1885.83,897.64 v1(1885.83,1173.23)
JP3_32: JP3.32 JP3A.32 | length 781.2
  Top Layer w6: JP3A.32 1440.94,496.06 1574.8,496.06 1885.83,807.09 JP3.32
JP3_33: JP3.33 JP3A.33 | length 1180.9
  Top Layer w7: JP3.33 v1(1917.33,1200.78)
  Bottom Layer w7: JP3A.33 1456.69,354.33 1456.69,433.07 1917.33,893.71 v1(1917.33,1200.78)
JP3_34: JP3.34 JP3A.34 | length 734
  Top Layer w6: JP3A.34 1503.94,480.31 1590.55,480.31 1917.33,807.09 JP3.34
JP3_35: JP3.35 JP3A.35 | length 1106.2
  Top Layer w7: JP3.35 v1(1948.83,1173.22)
  Bottom Layer w7: JP3A.35 1535.43,354.33 1535.43,429.13 1948.83,842.53 v1(1948.83,1173.22)
JP3_36: JP3.36 JP3A.36 | length 684.4
  Top Layer w6: JP3A.36 1566.93,464.57 1602.36,464.57 1948.83,811.03 JP3.36
JP3_37: JP3.37 JP3A.37 | length 1141.7
  Top Layer w6: JP3.37 v1(1980.33,1200.77)
  Bottom Layer w6: JP3A.37 1614.17,354.33 1614.17,429.13 1980.33,795.29 v1(1980.33,1200.77)
JP3_38: JP3.38 JP3A.38 | length 644.1
  Top Layer w6: JP3A.38 1574.8,401.58 1980.33,807.1 JP3.38
JP3_39: JP3.39 JP3A.39 | length 1067
  Top Layer w6: JP3.39 v1(2011.83,1173.21)
  Bottom Layer w6: JP3A.39 2011.83,673.24 v1(2011.83,1173.21)
JP3_40: JP3.40 JP3A.40 | length 624.5
  Top Layer w6: JP3A.40 1653.54,444.88 2011.83,803.17 JP3.40
JP3_42: JP3.42 JP3B.2 | length 605
  Top Layer w6: JP3B.2 1889.76,507.87 2200.83,818.94 JP3.42
JP3_44: JP3.44 JP3B.4 | length 585.4
  Top Layer w6: JP3B.4 1968.5,551.18 2232.33,815.01 JP3.44
JP3_45: JP3.45 JP3B.5 | length 1096
  Top Layer w7: JP3.45 v1(2263.83,1200.74)
  Bottom Layer w7: JP3B.5 2007.87,354.33 2007.87,468.5 2263.83,724.46 v1(2263.83,1200.74)
JP3_46: JP3.46 JP3B.6 | length 565.8
  Top Layer w6: JP3B.6 2047.24,590.55 2263.83,807.14 JP3.46
JP3_47: JP3.47 JP3B.7 | length 1021.3
  Top Layer w7: JP3.47 v1(2295.33,1173.18)
  Bottom Layer w7: JP3B.7 2086.61,354.33 2086.61,452.76 2295.33,661.47 v1(2295.33,1173.18)
JP3_48: JP3.48 JP3B.8 | length 546.3
  Top Layer w6: JP3B.8 2125.99,637.8 2295.33,807.14 JP3.48
JP3_49: JP3.49 JP3B.9 | length 1056.9
  Top Layer w7: JP3.49 v1(2326.83,1200.73)
  Bottom Layer w7: JP3B.9 2165.35,354.33 2165.35,448.82 2326.83,610.29 v1(2326.83,1200.73)
JP3_50: JP3.50 JP3B.10 | length 526.7
  Top Layer w6: JP3B.10 2204.73,681.1 2326.83,803.21 JP3.50
JP3_51: JP3.51 JP3B.11 | length 982.2
  Top Layer w7: JP3.51 v1(2358.33,1173.17)
  Bottom Layer w7: JP3B.11 2244.09,354.33 2244.09,452.76 2358.33,566.99 v1(2358.33,1173.17)
JP3_52: JP3.52 JP3B.12 | length 507.1
  Top Layer w6: JP3B.12 2283.47,732.28 2358.33,807.15 JP3.52
JP3_53: JP3.53 JP3B.13 | length 1017.7
  Top Layer w7: JP3.53 v1(2389.83,1200.72)
  Bottom Layer w7: JP3B.13 2322.83,354.33 2322.83,464.57 2389.83,531.56 v1(2389.83,1200.72)
JP3_54: JP3.54 JP3B.14 | length 487.6
  Top Layer w6: JP3B.14 2362.21,779.53 2389.83,807.15 JP3.54
JP3_55: JP3.55 JP3B.15 | length 943
  Top Layer w7: JP3.55 v1(2421.33,1173.16)
  Bottom Layer w7: v1(2421.33,1173.16) 2421.33,511.88 2401.57,492.13 2401.57,354.33 JP3B.15
JP3_56: JP3.56 JP3B.16 | length 484.3
  Top Layer w6: JP3.56 2421.33,810.96 2440.95,791.34 JP3B.16
JP3_57: JP3.57 JP3B.17 | length 1001.3
  Top Layer w7: JP3.57 v1(2452.83,1200.72)
  Bottom Layer w7: v1(2452.83,1200.72) 2452.83,484.18 2480.32,456.69 2480.32,354.33 JP3B.17
JP3_58: JP3.58 JP3B.18 | length 503.8
  Top Layer w6: JP3.58 2452.83,814.89 2519.69,748.03 JP3B.18
JP3_59: JP3.59 JP3B.19 | length 965.8
  Top Layer w7: JP3.59 v1(2484.33,1173.15)
  Bottom Layer w7: v1(2484.33,1173.15) 2484.33,507.8 2559.06,433.07 2559.06,354.33 JP3B.19
JP3_60: JP3.60 JP3B.20 | length 523.4
  Top Layer w6: JP3.60 2484.33,818.82 2598.43,704.72 JP3B.20
JP3_61: JP3.61 JP3B.21 | length 1040.4
  Top Layer w7: JP3.61 v1(2515.83,1200.71)
  Bottom Layer w7: v1(2515.83,1200.71) 2515.83,558.98 2637.8,437.01 2637.8,354.33 JP3B.21
JP3_62: JP3.62 JP3B.22 | length 543
  Top Layer w6: JP3.62 2515.83,810.94 2677.17,649.61 JP3B.22
JP3_63: JP3.63 JP3B.23 | length 1004.9
  Top Layer w7: JP3.63 v1(2547.33,1173.14)
  Bottom Layer w7: v1(2547.33,1173.14) 2547.33,614.09 2712.6,448.82 2712.6,358.27 JP3B.23
JP3_64: JP3.64 JP3B.24 | length 562.5
  Top Layer w6: JP3.64 2547.33,807 2755.91,598.43 JP3B.24
JP3_65: JP3.65 JP3B.25 | length 1079.6
  Top Layer w7: JP3.65 v1(2578.83,1200.7)
  Bottom Layer w7: v1(2578.83,1200.7) 2578.83,649.52 2795.28,433.07 2795.28,354.33 JP3B.25
JP3_66: JP3.66 JP3B.26 | length 582.1
  Top Layer w6: JP3.66 2578.83,803.06 2834.65,547.24 JP3B.26
JP3_67: JP3.67 JP3B.27 | length 1044
  Top Layer w7: JP3.67 v1(2610.33,1173.14)
  Bottom Layer w7: v1(2610.33,1173.14) 2610.33,704.63 2874.02,440.94 2874.02,354.33 JP3B.27
JP3_68: JP3.68 JP3B.28 | length 601.7
  Top Layer w6: JP3.68 2610.33,806.99 2913.39,503.94 JP3B.28
JP3_69: JP3.69 JP3B.29 | length 1118.7
  Top Layer w7: JP3.69 v1(2641.83,1200.69)
  Bottom Layer w7: v1(2641.83,1200.69) 2641.83,755.81 2952.76,444.88 2952.76,354.33 JP3B.29
JP3_70: JP3.70 JP3B.30 | length 621.2
  Top Layer w6: JP3.70 2641.83,803.25 2992.13,452.95 JP3B.30
JP3_71: JP3.71 JP3B.31 | length 1099.2
  Top Layer w7: JP3.71 v1(2673.33,1173.13)
  Bottom Layer w7: v1(2673.33,1173.13) 2673.33,771.75 2966.48,478.6 2993.85,478.6 3031.5,440.94 3031.5,354.33 JP3B.31
JP3_72: JP3.72 JP3B.32 | length 666.2
  Top Layer w6: JP3.72 2673.33,803.05 3007.87,468.5 3051.18,468.5 3070.87,448.82 JP3B.32
JP3_73: JP3.73 JP3B.33 | length 1197
  Top Layer w7: JP3.73 v1(2704.83,1200.68)
  Bottom Layer w7: v1(2704.83,1200.68) 2704.83,779.42 2984.25,500 3051.18,500 3110.24,440.94 3110.24,354.33 JP3B.33
JP3_74: JP3.74 JP3B.34 | length 681
  Top Layer w6: JP3.74 2704.83,803.25 3023.83,484.25 3059.06,484.25 JP3B.34
JP3_75: JP3.75 JP3B.35 | length 1189.1
  Top Layer w7: JP3.75 v1(2736.33,1173.12)
  Bottom Layer w7: v1(2736.33,1173.12) 2736.33,775.48 2992.13,519.68 3106.3,519.68 3188.98,437.01 3188.98,354.33 JP3B.35
JP3_76: JP3.76 JP3B.36 | length 726.1
  Top Layer w6: JP3.76 2736.33,806.98 3043.31,500 3122.05,500 JP3B.36
JP3_77: JP3.77 JP3B.37 | length 1289.2
  Top Layer w7: JP3.77 v1(2767.83,1200.68)
  Bottom Layer w7: v1(2767.83,1200.68) 2767.83,783.35 3003.94,547.24 3161.42,547.24 3267.72,440.94 3267.72,354.33 JP3B.37
JP3_78: JP3.78 JP3B.38 | length 773.3
  Top Layer w6: JP3.78 2767.83,806.98 3055.12,519.68 3181.1,519.68 JP3B.38
JP3_79: JP3.79 JP3B.39 | length 1272.1
  Top Layer w7: JP3.79 v1(2799.33,1173.11)
  Bottom Layer w7: v1(2799.33,1173.11) 2799.33,787.29 3019.69,566.93 3208.66,566.93 3346.46,429.13 3346.46,354.33 JP3B.39
JP3_80: JP3.80 JP3B.40 | length 820.4
  Top Layer w6: JP3.80 2799.33,807.2 3067.16,539.37 3240.16,539.37 JP3B.40
JP3_81: JP3.81 JP3C.1 | length 1286.7
  Top Layer w7: JP3.81 v1(2988.33,1200.65)
  Bottom Layer w7: v1(2988.33,1200.65) 2988.33,862.07 3535.43,314.96 JP3C.1
JP3_82: JP3.82 JP3C.2 | length 867.8
  Top Layer w6: JP3.82 2988.33,806.95 3236.22,559.06 3456.69,559.06 JP3C.2
JP3_83: JP3.83 JP3C.3 | length 1274.2
  Top Layer w7: JP3.83 v1(3019.83,1173.09)
  Bottom Layer w7: v1(3019.83,1173.09) 3019.83,869.94 3535.43,354.33 3661.42,354.33 JP3C.3
JP3_84: JP3.84 JP3C.4 | length 910.4
  Top Layer w6: JP3.84 3019.83,814.82 3259.84,574.8 3519.68,574.8 JP3C.4
JP3_86: JP3.86 JP3C.6 | length 957.7
  Top Layer w6: JP3.86 3051.33,814.81 3275.59,590.55 3582.68,590.55 JP3C.6
JP3_88: JP3.88 JP3C.8 | length 1007.2
  Top Layer w6: JP3.88 3082.83,810.87 3287.4,606.3 3645.67,606.3 JP3C.8
JP3_89: JP3.89 JP3C.9 | length 1491.8
  Top Layer w7: JP3.89 v1(3114.33,1200.63)
  Bottom Layer w7: v1(3114.33,1200.63) 3114.33,905.36 3559.06,460.63 3862.2,460.63 3897.64,425.2 3897.64,354.33 JP3C.9
JP3_90: JP3.90 JP3C.10 | length 1056.8
  Top Layer w6: JP3.90 3114.33,806.93 3299.21,622.05 3708.66,622.05 JP3C.10
JP3_91: JP3.91 JP3C.11 | length 1486.2
  Top Layer w7: JP3.91 v1(3145.83,1173.07)
  Bottom Layer w7: v1(3145.83,1173.07) 3145.83,897.48 3566.93,476.38 3921.26,476.38 3976.38,421.26 3976.38,354.33 JP3C.11
JP3_92: JP3.92 JP3C.12 | length 1104
  Top Layer w6: JP3.92 3145.83,806.93 3314.96,637.8 3771.65,637.8 JP3C.12
JP3_93: JP3.93 JP3C.13 | length 1600.1
  Top Layer w7: JP3.93 v1(3177.33,1200.62)
  Bottom Layer w7: v1(3177.33,1200.62) 3177.33,889.6 3574.8,492.13 3996.06,492.13 4055.12,433.07 4055.12,354.33 JP3C.13
JP3_94: JP3.94 JP3C.14 | length 1153.5
  Top Layer w6: JP3.94 3177.33,802.99 3326.77,653.54 3834.65,653.54 JP3C.14
JP3_95: JP3.95 JP3C.15 | length 1596.8
  Top Layer w7: JP3.95 v1(3208.83,1173.06)
  Bottom Layer w7: v1(3208.83,1173.06) 3208.83,881.72 3582.68,507.87 4059.06,507.87 4133.86,433.07 4133.86,354.33 JP3C.15
JP3_96: JP3.96 JP3C.16 | length 1198.5
  Top Layer w6: JP3.96 3208.83,806.92 3346.46,669.29 3897.64,669.29 JP3C.16
JP3_97: JP3.97 JP3C.17 | length 1699.2
  Top Layer w7: JP3.97 v1(3240.33,1200.62)
  Bottom Layer w7: v1(3240.33,1200.62) 3240.33,873.85 3590.55,523.62 4114.17,523.62 4212.6,425.2 4212.6,354.33 JP3C.17
JP3_98: JP3.98 JP3C.18 | length 1245.7
  Top Layer w6: JP3.98 3240.33,806.92 3362.2,685.04 3960.63,685.04 JP3C.18
JP3_99: JP3.99 JP3C.19 | length 1700.5
  Top Layer w7: JP3.99 v1(3271.83,1173.05)
  Bottom Layer w7: v1(3271.83,1173.05) 3271.83,869.9 3598.43,543.31 4185.04,543.31 4291.34,437.01 4291.34,354.33 JP3C.19
JP3_100: JP3.100 JP3C.20 | length 1295.3
  Top Layer w6: JP3.100 3271.83,802.98 3374.02,700.79 4023.62,700.79 JP3C.20
JP3_101: JP3.101 JP3C.21 | length 1786.8
  Top Layer w7: JP3.101 v1(3303.33,1200.61)
  Bottom Layer w7: v1(3303.33,1200.61) 3303.33,905.33 3645.67,562.99 4251.97,562.99 4370.08,444.88 4370.08,354.33 JP3C.21
JP3_102: JP3.102 JP3C.22 | length 1340.2
  Top Layer w6: JP3.102 3303.33,806.91 3393.7,716.54 4086.61,716.54 JP3C.22
JP3_103: JP3.103 JP3C.23 | length 1765
  Top Layer w7: JP3.103 v1(3334.83,1173.05)
  Bottom Layer w7: v1(3334.83,1173.05) 3334.83,913.2 3669.29,578.74 4299.21,578.74 4448.82,429.13 4448.82,354.33 JP3C.23
JP3_104: JP3.104 JP3C.24 | length 1385.1
  Top Layer w6: JP3.104 3334.83,810.84 3413.39,732.28 4149.61,732.28 JP3C.24
JP3_105: JP3.105 JP3C.25 | length 1878.9
  Top Layer w7: JP3.105 v1(3366.33,1200.6)
  Bottom Layer w7: v1(3366.33,1200.6) 3366.33,909.26 3681.1,594.49 4377.95,594.49 4527.56,444.88 4527.56,354.33 JP3C.25
JP3_107: JP3.107 JP3C.27 | length 1877.9
  Top Layer w7: JP3.107 v1(3397.83,1173.04)
  Bottom Layer w7: v1(3397.83,1173.04) 3397.83,909.26 3692.91,614.17 4448.82,614.17 4606.3,456.69 4606.3,354.33 JP3C.27
JTAG_TCK: JP1.6 JP2.114 | length 2152.5
  Top Layer w7: JP2.114 3602.56,2326.57 4665.35,1263.78 4759.84,1263.78 JP1.6
JTAG_TDI: JP1.10 JP2.113 | length 2888
  Top Layer w7: JP2.113 3602.56,3118.31 3665.35,3181.1 3814.96,3181.1 4893.7,2102.36 4893.7,1161.42 JP1.10
JTAG_TDO: JP1.8 JP2.115 | length 2704.4
  Top Layer w7: JP2.115 3634.06,3110.44 3681.1,3157.48 3799.21,3157.48 4862.2,2094.49 4862.2,1208.66 JP1.8
JTAG_TMS: JP1.4 JP2.116 | length 2067.6
  Top Layer w7: JP2.116 3634.06,2362 4653.54,1342.52 4759.84,1342.52 JP1.4
USB_SCL: JP3.113 JP3C.33 | length 1992
  Top Layer w8: JP3.113 v1(3492.33,1173.03)
  Bottom Layer w8: v1(3492.33,1173.03) 3492.33,932.87 3787.4,637.8 4637.8,637.8 4842.52,433.07 4842.52,354.33 JP3C.33
USB_SDA: JP3.114 JP3C.34 | length 1628.3
  Top Layer w7: JP3.114 3492.33,799.01 3543.31,748.03 4527.56,748.03 JP3C.34
USER_PROG_B: JP2.120
pads on no net: JP1.12 JP1.14 JP2.105 JP2.107 JP2.109 JP2.110 JP2.111 JP2.112 JP2.118 JP2.N JP2C.25 JP2C.27 JP2C.29 JP2C.30 JP2C.31 JP2C.32 JP2C.33 JP2C.34 JP2C.35 JP2C.36 JP2C.38 JP2C.40 JP3.106 JP3.108 JP3.109 JP3.110 JP3.111 JP3.112 JP3.N JP3C.26 JP3C.28 JP3C.29 JP3C.30 JP3C.31 JP3C.32

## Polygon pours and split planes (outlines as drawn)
DGND on Bottom Layer "Bottom Layer-DGND" (solid, pour order 1000): 0,3937.01 5314.96,3937.01 5314.96,0 0,0

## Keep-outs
Keep-Out Layer:
  the board outline again, w7.01

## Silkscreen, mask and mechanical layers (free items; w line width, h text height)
Top Overlay:
  lines w7.99: 1023.62,1368.11 1023.62,767.72 1860.24,767.72 ; 1023.62,2568.9 1023.62,3169.29 1860.24,3169.29 ; 3533.46,767.72 4370.08,767.72 4370.08,1368.11 ; 3533.46,3169.29 4370.08,3169.29 4370.08,2568.9
  text "VCCO13" at 397.64,3807.09 h30
  text "VCCO17" at 2039.37,3803.15 h30
  text "+3.3V" at 4669.29,3799.21 h40
  text "VCCO21" at 3866.14,3791.34 h30
  text "DGND" at 673.23,2996.06 h40
  text "DGND" at 4740.16,2937.01 h40
  text "BRK5010" at 619,2322.27 h40 r90
  text "20100226" at 697.74,2322.27 h40 r90
  text "+3.3V" at 4900.31,1363.78 h40
  text "TMS" at 4900.31,1285.04 h40
  text "TCK" at 4900.31,1206.3 h40
  text "TDO" at 4900.31,1127.56 h40
  text "TDI" at 4900.31,1048.82 h40
  text "DGND" at 661.42,913.39 h40
  text "DGND" at 4854.33,574.8 h40
  text "+1.0V" at 4846.46,185.04 h30
  text "VCCO14" at 2011.81,106.3 h30
  text "VCCO18" at 3885.83,106.3 h30
  text "+VDC" at 4461.58,106.3 h30
  text "VCCO3" at 429.13,102.36 h30
Top Solder:
  lines w1: 4370.08,0 0,0 0,3937.01 4370.08,3937.01 ; 5314.96,0 5314.96,3937.01
Mechanical 2:
  the board outline again, w8
Drill Drawing:
  lines w10: 3308.03,-677.68 6703.78,-677.68 ; 3308.03,-503.68 6703.78,-503.68 ; 3248.03,-1101.48 ccw(c3304.03,-1101.48) 3304.03,-1157.48 6707.78,-1157.48 ccw(c6707.78,-1101.48) 6763.78,-1101.48 6763.78,-422.14 ccw(c6707.78,-422.14) 6707.78,-366.14 3304.03,-366.14 ccw(c3304.03,-422.14) 3248.03,-422.14 3248.03,-1101.48
  text ".LEGEND" at 5430.08,10.35 h50
  text "NOTES" at 64.15,-342.9 h50
  text "1. MATERIAL SELECTION:" at 64.15,-442.9 h50
  text "Layer Stack Up Detail for: EVB5010.PcbDoc" at 3308.03,-470.71 h51
  text "2-LAYER, 370HR, 0.62\" +/- 0.005 THICK" at 189.15,-517.9 h50
  text "Layer" at 3308.03,-568.68 h40
  text "Gerber" at 4116.1,-568.68 h40
  text "Copper" at 4709.17,-568.68 h40
  text "Dielectric" at 5367.55,-568.68 h40
  text "Dielectric" at 6053.93,-568.68 h40
  text "SURFACE FINISH: ENIG (ELECTROLESS NICKEL, IMMERSION GOLD)" at 189.15,-592.9 h50
  text "Name" at 3308.03,-648.68 h40
  text "Document" at 4116.1,-648.68 h40
  text "Thickness" at 4709.17,-648.68 h40
  text "Height" at 5367.55,-648.68 h40
  text "Material" at 6053.93,-648.68 h40
  text "2. SOLDER RESIST: GREEN LPI" at 64.15,-717.9 h50
  text "Top Layer" at 3308.03,-801.38 h56
  text "(.GTL)" at 4116.1,-801.38 h56
  text "1.4mil" at 4709.17,-801.38 h56
  text "3. SILKSCREEN: WHITE / DO NOT REMOVE OVER TENTED VIAS." at 64.15,-842.9 h50
  text "62mil" at 5367.55,-880.51 h56
  text "FR-4" at 6053.93,-880.51 h56
  text "Bottom Layer" at 3308.03,-959.65 h56
  text "(.GBL)" at 4116.1,-959.65 h56
  text "1.4mil" at 4709.17,-959.65 h56
  text "4. LOT CODE IDENTIFICATION: ADD TO SILKSCREEN" at 64.15,-967.9 h50
  text "5. DRILL SIZES ARE FINISHED SIZE AFTER PLATING." at 64.15,-1092.9 h50
  text "6. ELECTRICAL BARE BOARD TEST REQUIRED" at 64.15,-1217.9 h50
  text "7. FABRICATE TO MEET EU ROHS DIRECTIVE" at 64.15,-1342.9 h50
  text "8. PANELIZATION:" at 64.15,-1463.33 h50
  text "2-PIECES PER PANEL" at 189.15,-1538.33 h50
  text "0.25-IN RAILS ON ALL SIDES" at 189.15,-1613.33 h50
  text "0.25-IN TAB ROUTING WITH MOUSE-BITES FOR BOARD SEPARATION" at 189.15,-1688.33 h50

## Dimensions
118.11,3818.9 to 118.11,118.11 on Mechanical 1
0,0 to 0,3937.01 on Mechanical 1
118.11,118.11 to 5196.85,118.11 on Mechanical 1
0,0 to 5314.96,0 on Mechanical 1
